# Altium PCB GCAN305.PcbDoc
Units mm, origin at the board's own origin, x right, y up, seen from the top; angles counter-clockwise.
Board outline 152.4 x 101.6 mm, 2 copper layers (Top Layer, Bottom Layer); 1 components, 0 nets, 24 pads, 0 vias.
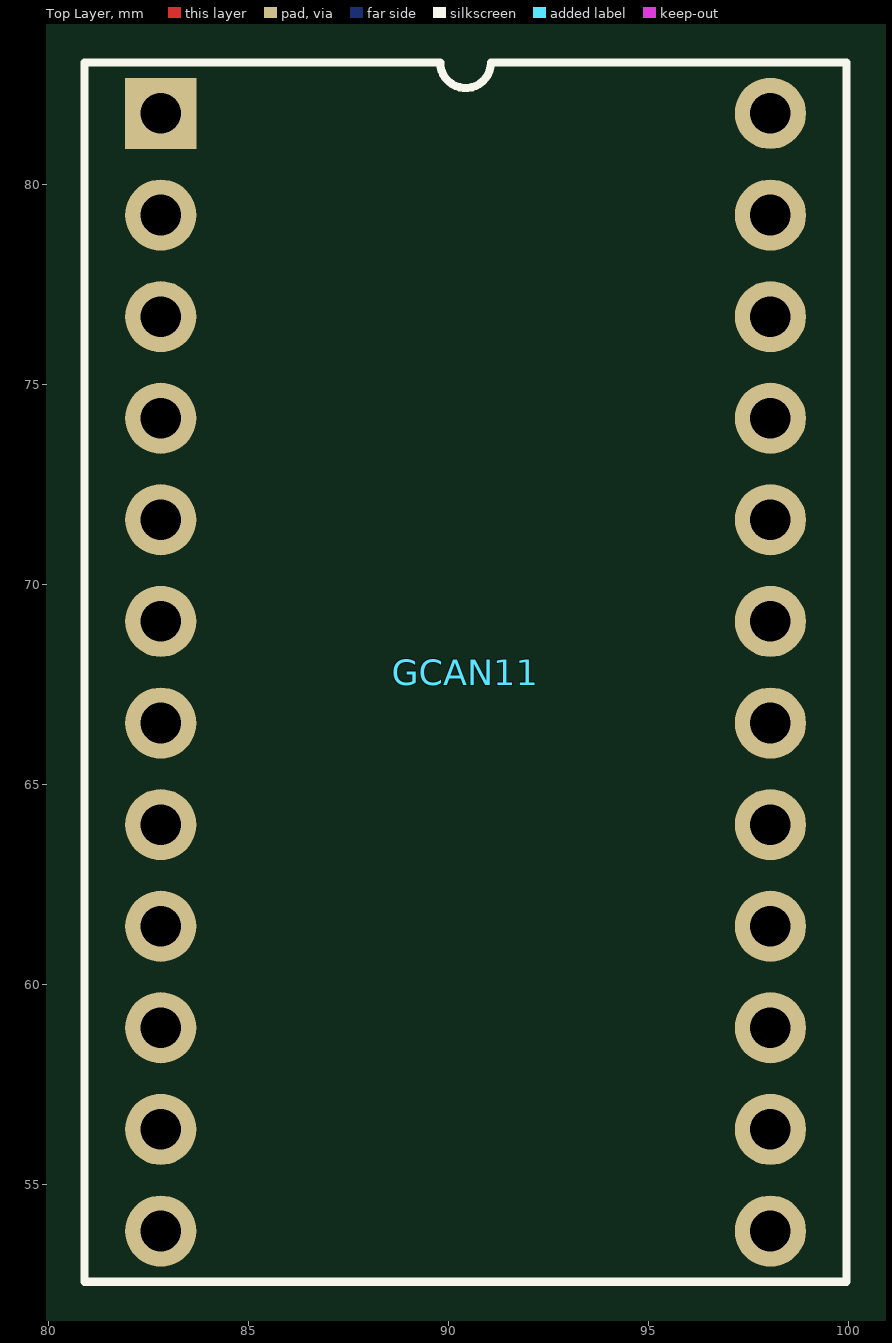
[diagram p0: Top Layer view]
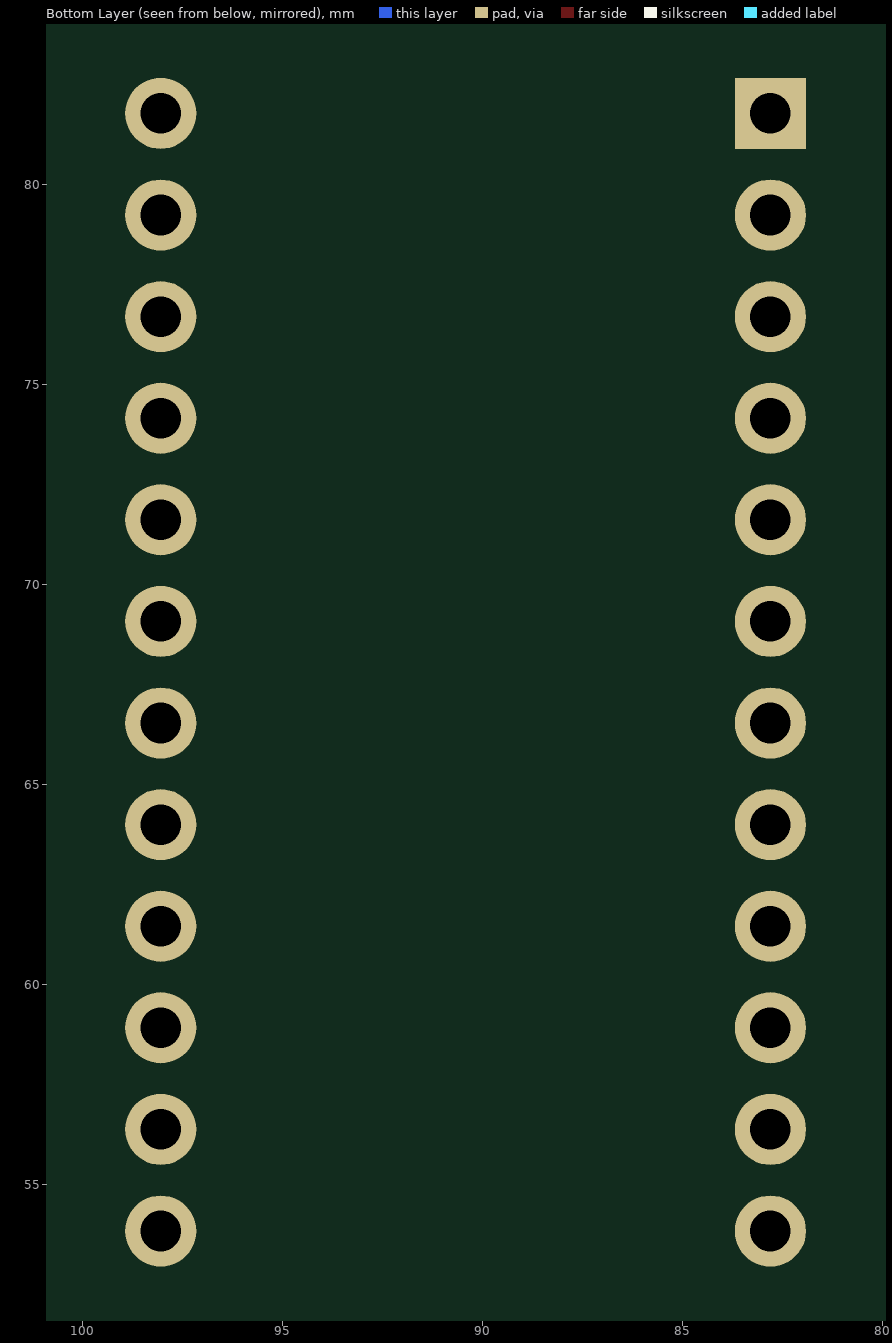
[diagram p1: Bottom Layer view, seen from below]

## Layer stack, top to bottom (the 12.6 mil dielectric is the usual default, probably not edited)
Top Layer: signal copper 0.0356
Dielectric: dielectric 0.32, FR-4, Dk 4.8
Bottom Layer: signal copper 0.0356

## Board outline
25.4,25.4 177.8,25.4 177.8,127 25.4,127

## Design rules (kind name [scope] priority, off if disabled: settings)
Clearance [All] p1: gap=0.254
PolygonConnect [All] p1: connectstyle=Relief reliefconductorwidth=0.254 reliefentries=4 polygonreliefangle="90 Angle"
RoutingVias [All] p1: holewidth=0.711 width=1.27 viastyle="Through Hole" minholewidth=0.711 minwidth=1.27 maxholewidth=0.711 maxwidth=1.27
SolderMaskExpansion [All] p1: expansion=0.102
TestPointUsage [All] p1: valid=0 allowmultiple=FALSE
Testpoint [All] p1: side=15 testpointundercomponent=TRUE minsize=1.016 maxsize=2.54 preferedsize=1.524 minholesize=0 maxholesize=1.016 preferedholesize=0.813 testpointgrid=0.025 style=1023 order=0-112345678
Width [All] p1: maxlimit=0.254 minlimit=0.254 preferedwidth=0.254
19 further rules are at their usual default settings.

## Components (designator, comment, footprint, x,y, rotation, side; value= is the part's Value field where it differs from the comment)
GCAN11 "Comment" DIP24 82.804,81.788 r0 top

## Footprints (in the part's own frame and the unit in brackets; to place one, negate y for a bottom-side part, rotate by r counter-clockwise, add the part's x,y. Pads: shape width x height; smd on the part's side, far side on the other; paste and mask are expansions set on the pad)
DIP24 [mil]
  rect 70x70 hole 40: 1(0,0)
  round 70 hole 40: 2(0,-100) 3(0,-200) 4(0,-300) 5(0,-400) 6(0,-500) 7(0,-600) 8(0,-700) 9(0,-800) 10(0,-900) 11(0,-1000) 12(0,-1100) 13(600,-1100) 14(600,-1000) 15(600,-900) 16(600,-800) 17(600,-700) 18(600,-600) 19(600,-500) 20(600,-400) 21(600,-300) 22(600,-200) 23(600,-100) 24(600,0)
  silkscreen extent -75,-1150 675,50

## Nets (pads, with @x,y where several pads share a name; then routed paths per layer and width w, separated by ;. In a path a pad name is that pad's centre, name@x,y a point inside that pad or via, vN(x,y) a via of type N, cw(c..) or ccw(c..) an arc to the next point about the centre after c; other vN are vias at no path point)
pads on no net: GCAN11.1 GCAN11.2 GCAN11.3 GCAN11.4 GCAN11.5 GCAN11.6 GCAN11.7 GCAN11.8 GCAN11.9 GCAN11.10 GCAN11.11 GCAN11.12 GCAN11.13 GCAN11.14 GCAN11.15 GCAN11.16 GCAN11.17 GCAN11.18 GCAN11.19 GCAN11.20 GCAN11.21 GCAN11.22 GCAN11.23 GCAN11.24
